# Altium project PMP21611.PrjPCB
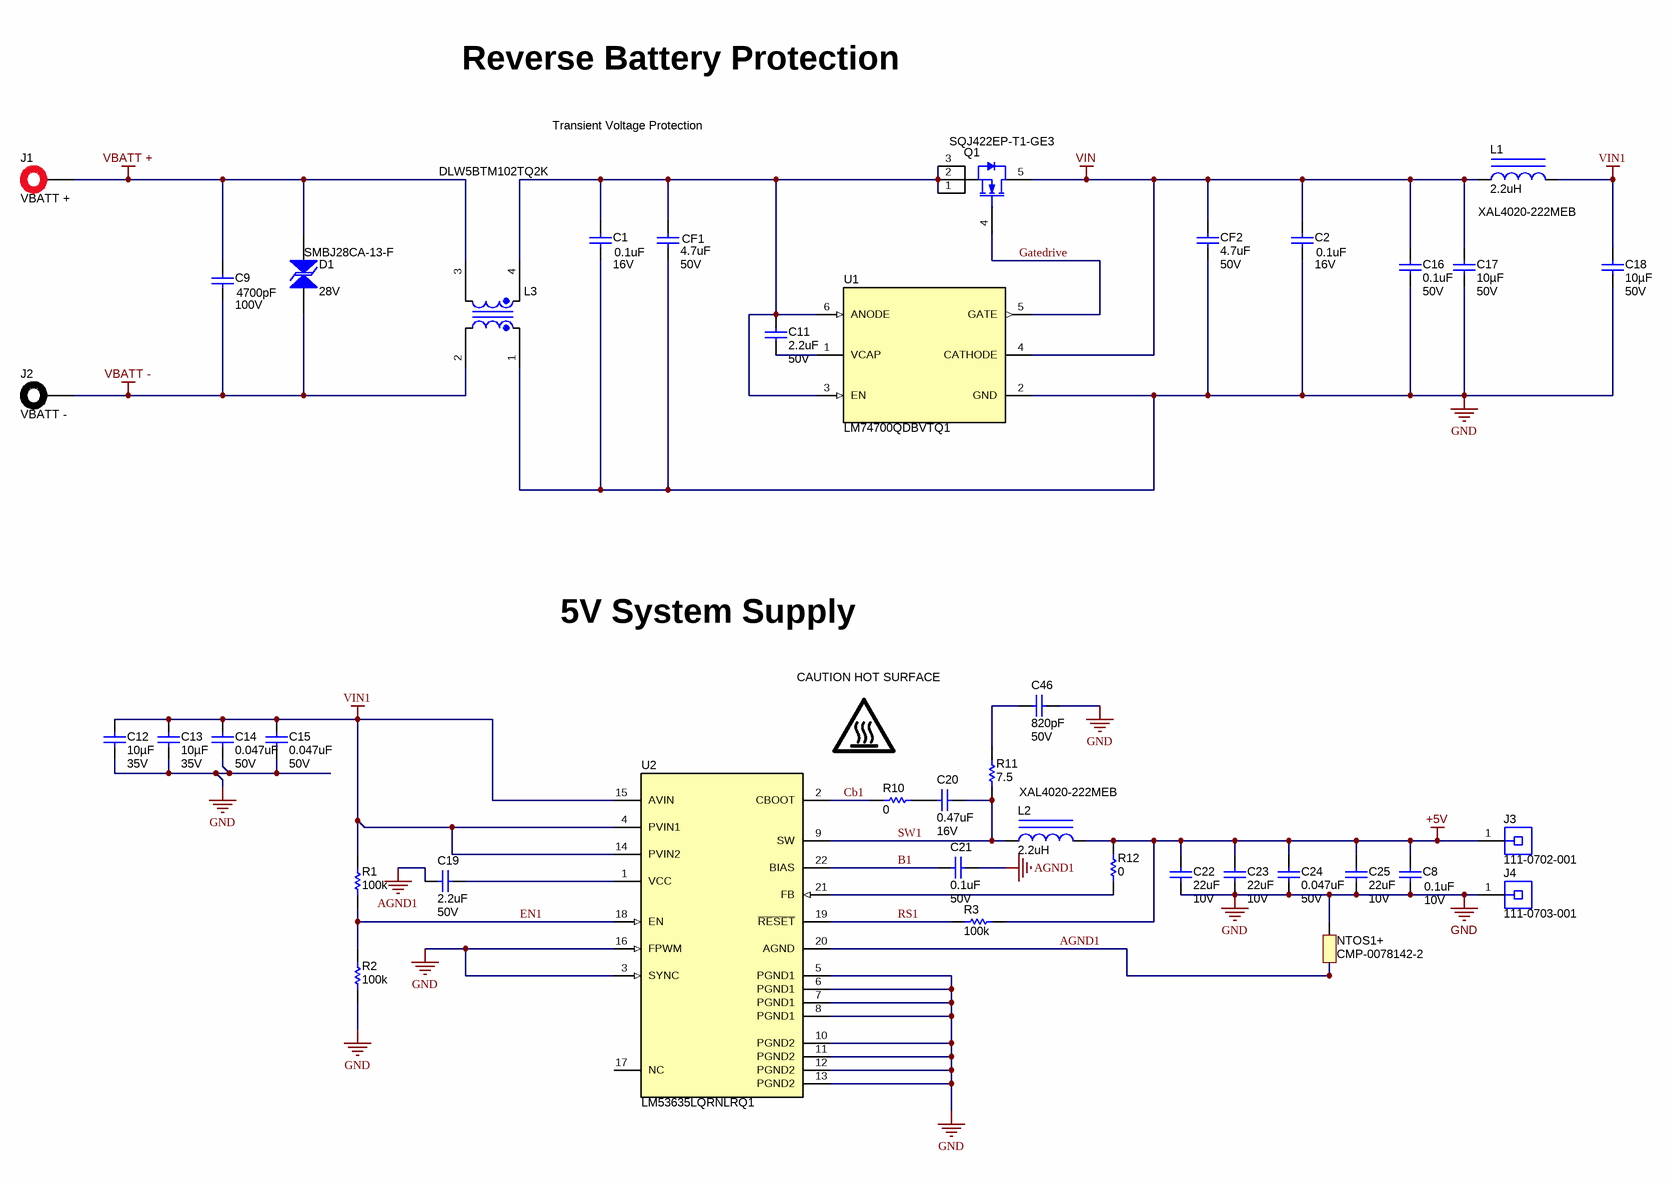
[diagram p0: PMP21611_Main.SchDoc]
CopyrightYear: 2018; EVM_Orderable: N/A; PCB_Layout: Dee Lim; PCB_Rev: A; PRJ_Customer: Public Release; PRJ_Engineer: R. Sheehan/ D. Foncannon; PRJ_Number: PMP21611; PRJ_Title: Automotive TFT Cluster Power Supply; SCH_Rev: A; TechSupport: http://www.ti.com/support
4 sheets, 96 parts. Net scope: global (net labels, ports and power ports of the same name join across sheets).
Board file: PMP21611.PcbDoc
Sheets:
  PMP21611_Cover.SchDoc
  PMP21611_Main.SchDoc
  PMP21611_Dual.SchDoc
  PMP21611_Hardware.SchDoc

## Sheet PMP21611_Cover.SchDoc
size 431 x 279 mm; Date: Not shown in title block; ApprovedBy: Not shown in title block; CheckedBy: Not shown in title block; Author: Not shown in title block; CompanyName: Not shown in title block; Engineer: Not shown in title block; Organization: Not shown in title block; Address1: Not shown in title block; Address2: Not shown in title block; Address3: Not shown in title block; Address4: Not shown in title block; DocumentNumber: 1; Revision: Use project parameter SCH_Rev; SheetNumber: 1; SheetTotal: 4; PageSetup: Record=PageOptions¦CenterHorizontal=True¦CenterVertical=True¦PrintScale=1.00¦XCorrection=1.00¦YCorrection=1.00¦PrintKind=0¦BorderSize=5000000¦LeftOffset=0¦BottomOffset=0¦Orientation=2¦PaperLength=1000¦PaperWidth=1000¦Scale=100¦PaperSource=15¦PrintQuality=600¦MediaType=1¦DitherType=10¦PaperKind=Letter¦PrintScaleMode=1

## Sheet PMP21611_Main.SchDoc
size 431 x 279 mm; Date: Not shown in title block; ApprovedBy: Not shown in title block; CheckedBy: Not shown in title block; Author: Not shown in title block; CompanyName: Not shown in title block; Engineer: Not shown in title block; Organization: Not shown in title block; Address1: Not shown in title block; Address2: Not shown in title block; Address3: Not shown in title block; Address4: Not shown in title block; DocumentNumber: 2; Revision: Use project parameter SCH_Rev; SheetNumber: 2; SheetTotal: 4; PageSetup: Record=PageOptions¦CenterHorizontal=True¦CenterVertical=True¦PrintScale=1.00¦XCorrection=1.00¦YCorrection=1.00¦PrintKind=0¦BorderSize=5000000¦LeftOffset=0¦BottomOffset=0¦Orientation=2¦PaperLength=1000¦PaperWidth=1000¦Scale=100¦PaperSource=15¦PrintQuality=600¦MediaType=1¦DitherType=10¦PaperKind=Letter¦PrintScaleMode=1

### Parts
(Parts that share a designator on the sheet are numbered #1, #2 ... from top to bottom, then left to right.)
C1  ValueDisplayed: 0.1uF  VDC_V: 16V  [0603]  (hidden comment: CMP-0007135-4)
C2  ValueDisplayed: 0.1uF  VDC_V: 16V  [0603]  (hidden comment: CMP-0007135-4)
C8  VDC_V: 10V  ValueDisplayed: 0.1uF  [0402]  (hidden comment: GCM155R71A104KA55D)
C9  ValueDisplayed: 4700pF  VDC_V: 100V  [0603]  (hidden comment: 06031C472KAT2A)
C11  ValueDisplayed: 2.2uF  VDC_V: 50V  [1206_180]  (hidden comment: C3216X7R1H225K160AB)
C12  ValueDisplayed: 10µF  VDC_V: 35V  [1210_270]  (hidden comment: GRM32ER7YA106KA12K)
C13  ValueDisplayed: 10µF  VDC_V: 35V  [1210_270]  (hidden comment: GRM32ER7YA106KA12K)
C14  ValueDisplayed: 0.047uF  VDC_V: 50V  [0603]  (hidden comment: C1608X7R1H473K080AA)
C15  ValueDisplayed: 0.047uF  VDC_V: 50V  [0603]  (hidden comment: C1608X7R1H473K080AA)
C16  ValueDisplayed: 0.1uF  VDC_V: 50V  [0805_HV]  (hidden comment: C0805C104K5RACTU)
C17  ValueDisplayed: 10µF  VDC_V: 50V  [1210_270]  (hidden comment: CL32B106KBJNNWE)
C18  ValueDisplayed: 10µF  VDC_V: 50V  [1210_270]  (hidden comment: CL32B106KBJNNWE)
C19  ValueDisplayed: 2.2uF  VDC_V: 50V  [1206_180]  (hidden comment: C3216X7R1H225K160AB)
C20  ValueDisplayed: 0.47uF  VDC_V: 16V  [0603]  (hidden comment: GCM188R71C474KA55D)
C21  ValueDisplayed: 0.1uF  VDC_V: 50V  [0603]  (hidden comment: GRM188R71H104KA93D)
C22  ValueDisplayed: 22uF  VDC_V: 10V  [1210_270]  (hidden comment: GRM32ER71A226ME20L)
C23  ValueDisplayed: 22uF  VDC_V: 10V  [1210_270]  (hidden comment: GRM32ER71A226ME20L)
C24  ValueDisplayed: 0.047uF  VDC_V: 50V  [0805_HV]  (hidden comment: 08055C473JAT2A)
C25  ValueDisplayed: 22uF  VDC_V: 10V  [1210_270]  (hidden comment: GRM32ER71A226ME20L)
C46  ValueDisplayed: 820pF  VDC_V: 50V  [0603]  (hidden comment: C0603C821K5RACTU)
CF1  ValueDisplayed: 4.7uF  VDC_V: 50V  [1210_280]  (hidden comment: CMP-0009163-2)
CF2  ValueDisplayed: 4.7uF  VDC_V: 50V  [1210_280]  (hidden comment: CMP-0009163-2)
D1  value 28V  PartNumber: SMBJ28CA-13-F  [SMB-Bi]  (hidden comment: CMP-0006046-2)
J1  VBATT +  [6091]
J2  VBATT -  [6092]
J3  111-0702-001  [Emerson_111-0702-001]
J4  111-0703-001  [Emerson_111-0703-001]
L1  PartNumber: XAL4020-222MEB  ValueDisplayed: 2.2uH  [XAL4020]  (hidden comment: CMP-0060986-1)
L2  PartNumber: XAL4020-222MEB  ValueDisplayed: 2.2uH  [XAL4020]  (hidden comment: CMP-0060986-1)
L3  PartNumber: DLW5BTM102TQ2K  [DLW5BT_TQ2]  (hidden comment: CMP-0076877-1)
LOGO4#1  CAUTION HOT SURFACE  [IEC_HotSurface_Small]  (no BOM)
NTOS1+  CMP-0078142-2  [Net-Tie_10mil]  (net tie, no BOM)
Q1  PartNumber: SQJ422EP-T1-GE3  [PowerPAK_SO-8L]  (hidden comment: CMP-0000747-1)
R1  ValueDisplayed: 100k  [0603]  (hidden comment: CRCW0603100KFKEA)
R2  ValueDisplayed: 100k  [0603]  (hidden comment: CRCW0603100KFKEA)
R3  ValueDisplayed: 100k  [0805_HV]  (hidden comment: CRCW0805100KFKEA)
R10  ValueDisplayed: 0  [0603]  (hidden comment: RMCF0603ZT0R00)
R11  ValueDisplayed: 7.5  [0603]  (hidden comment: CRCW06037R50JNEA)
R12  ValueDisplayed: 0  [0603]  (hidden comment: RMCF0603ZT0R00)
U1  LM74700QDBVTQ1  [DBV0006A_N]
U2  LM53635LQRNLRQ1  [RNL0022A]

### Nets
+5V: C8.1 C22.1 C23.1 C24.1 C25.1 J3.1 L2.2 R3.2 R12.2
AGND1: C19.2 C21.1 NTOS1+.1 U2.20(AGND)
GND: C1.2 C2.2 C8.2 C12.2 C13.2 C14.2 C15.2 C16.2 C17.2 C18.2 C22.2 C23.2 C24.2 C25.2 C46.2 CF1.2 CF2.2 J4.1 L3.1 NTOS1+.2 R2.1 U1.2(GND) U2.3(SYNC) U2.5(PGND1) U2.6(PGND1) U2.7(PGND1) U2.8(PGND1) U2.10(PGND2) U2.11(PGND2) U2.12(PGND2) U2.13(PGND2) U2.16(FPWM)
VBATT +: C9.1 D1.1 J1.1 L3.3
VBATT -: C9.2 D1.2 J2.1 L3.2
VIN: C2.1 C16.1 C17.1 CF2.1 L1.1 Q1.5(D) U1.4(CATHODE)
VIN1: C12.1 C13.1 C14.1 C15.1 C18.1 L1.2 R1.2 U2.4(PVIN1) U2.14(PVIN2) U2.15(AVIN)
B1: C21.2 U2.22(BIAS)
Cb1: R10.1 U2.2(CBOOT)
EN1: R1.1 R2.2 U2.18(EN)
Gatedrive: Q1.4(G) U1.5(GATE)
RS1: R3.1 U2.19(~{RESET})
SW1: C20.1 L2.1 R11.1 U2.9(SW)
NetC1_1: C1.1 C11.1 CF1.1 L3.4 Q1.1(S) Q1.2(S) Q1.3(S) U1.3(EN) U1.6(ANODE)
NetC11_2: C11.2 U1.1(VCAP)
NetC19_1: C19.1 U2.1(VCC)
NetC20_2: C20.2 R10.2
NetC46_1: C46.1 R11.2
NetR12_1: R12.1 U2.21(FB)

Not connected (* = marked no-connect by the designer): U2 17(NC)

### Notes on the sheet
- Reverse Battery Protection
- Transient Voltage Protection
- 5V System Supply

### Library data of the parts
C1 C2 = CMP-0007135-4: CAP, CERM, 0.1 uF, 16 V, +/- 10%, X7R, AEC-Q200 Grade 1, 0603; PartNumber: GCM188R71C104KA37J; Manufacturer: MuRata; Polarized: N; Value: 0.1uF; U/M: EA; Cap_F: 100nF; Value1: Unknown; TaMin_C: -55°C; TaMax_C: 125°C; AEC Category: Q200; AEC Qualified: Y; AEC Grade: 1; SizeArea_mm2: 1.28; SizeAreaWB_mm2: 4.68; SizeX_mm: 1.6; SizeY_mm: 0.8
C8 = CMP-0006350-2: CAP, CERM, 0.1 uF, 10 V, +/- 10%, X7R, AEC-Q200 Grade 1, 0402; Manufacturer: MuRata; TaMin_C: -55°C; Polarized: N; SizeAreaWB_mm2: 3; Value1: Unknown; U/M: EA; Value: 0.1uF; TaMax_C: 125°C; SizeZ_mm: 0.6; SizeX_mm: 1; SizeY_mm: 0.5; AEC Qualified: Y; Cap_F: 100nF; AEC Category: Q200
C9 = CMP-0006746-5: CAP, CERM, 4700 pF, 100 V, +/- 10%, X7R, 0603; Manufacturer: AVX; Polarized: N; Value: 4700pF; U/M: EA; Cap_F: 4.7nF; ESR_ohm: 1.36d; Value1: 0.136 ohm; TaMin_C: -55°C; TaMax_C: 125°C; SizeArea_mm2: 1.28; SizeAreaWB_mm2: 4.68; SizeX_mm: 1.6; SizeY_mm: 0.8; SizeZ_mm: 1; AEC Category: Q200
C11 = CMP-0008698-2: CAP, CERM, 2.2 uF, 50 V, +/- 10%, X7R, 1206; Manufacturer: TDK; Value: 2.2uF; Polarized: N; U/M: EA; Cap_F: 2.2µF; ESR_ohm: 5.887m; Value1: 0.005887 ohm; IRMS_A: 2.99226A; TaMin_C: -55°C; TaMax_C: 125°C; SizeAreaWB_mm2: 10.92; SizeZ_mm: 1.8; SizeX_mm: 3.2; SizeY_mm: 1.6; SizeArea_mm2: 5.12; AEC Category: Q200
C12 = CMP-0081639-1: CAP, CERM, 10 µF, 35 V,+/- 10%, X7R, 1210; Manufacturer: MuRata; Polarized: N; Value: 10uF; U/M: EA; ESR_ohm: 1m; Value1: 0.001 ohm; IRMS_A: 6A; TaMin_C: -55°C; TaMax_C: 125°C; Cap_Case: 1210; SizeAreaWB_mm2: 14.7; SizeZ_mm: 2.7; SizeX_mm: 3.2; SizeY_mm: 2.5; SizeArea_mm2: 8; AEC Category: Q200
C13 = CMP-0081639-1: CAP, CERM, 10 µF, 35 V,+/- 10%, X7R, 1210; Manufacturer: MuRata; Polarized: N; CompType: Capacitor; Value: 10uF; U/M: EA; ESR_ohm: 1m; Value1: 0.001 ohm; IRMS_A: 6A; TaMin_C: -55°C; TaMax_C: 125°C; Cap_Case: 1210; SizeAreaWB_mm2: 14.7; SizeZ_mm: 2.7; SizeX_mm: 3.2; SizeY_mm: 2.5; SizeArea_mm2: 8; AEC Category: Q200
C14 = CMP-0007049-4: CAP, CERM, 0.047 uF, 50 V, +/- 10%, X7R, 0603; Manufacturer: TDK; Polarized: N; U/M: EA; Cap_F: 47nF; ESR_ohm: 0.049007; Value1: 0.049007 ohm; IRMS_A: 7.67528dA; TaMin_C: -55°C; TaMax_C: 125°C; SizeAreaWB_mm2: 4.68; SizeZ_mm: 1; SizeX_mm: 1.6; SizeY_mm: 0.8; SizeArea_mm2: 1.28; AEC Category: Q200
C15 = CMP-0007049-4: CAP, CERM, 0.047 uF, 50 V, +/- 10%, X7R, 0603; Manufacturer: TDK; Polarized: N; CompType: Capacitor; U/M: EA; Cap_F: 47nF; ESR_ohm: 0.049007; Value1: 0.049007 ohm; IRMS_A: 7.67528dA; TaMin_C: -55°C; TaMax_C: 125°C; SizeAreaWB_mm2: 4.68; SizeZ_mm: 1; SizeX_mm: 1.6; SizeY_mm: 0.8; SizeArea_mm2: 1.28; AEC Category: Q200
C16 = CMP-0007726-2: CAP, CERM, 0.1 uF, 50 V, +/- 10%, X7R, 0805; Manufacturer: Kemet; Polarized: N; Value: 0.1uF; U/M: EA; Cap_F: 100nF; ESR_ohm: 0.064; Value1: 0.064 ohm; IRMS_A: 1.64A; TaMin_C: -55°C; TaMax_C: 125°C; Cap_Case: 0805; SizeAreaWB_mm2: 6.75; SizeZ_mm: 1.45; SizeX_mm: 2; SizeY_mm: 1.25; SizeArea_mm2: 2.5; AEC Category: Q200
C17 C18 = CMP-0079201-1: CAP, CERM, 10 µF, 50 V,+/- 10%, X7R, 1210; Manufacturer: Samsung Electro-Mechanics; Polarized: N; CompType: Capacitor; Value: 10uF; U/M: EA; ESR_ohm: 5m; Value1: 0.005 ohm; TaMin_C: -55°C; TaMax_C: 125°C; Cap_Case: 1210; SizeAreaWB_mm2: 14.7; SizeZ_mm: 2.7; SizeX_mm: 3.2; SizeY_mm: 2.5; SizeArea_mm2: 8; AEC Category: Q200
C19 = CMP-0008698-2: CAP, CERM, 2.2 uF, 50 V, +/- 10%, X7R, 1206; Manufacturer: TDK; Polarized: N; CompType: Capacitor; Value: 2.2uF; U/M: EA; Cap_F: 2.2µF; ESR_ohm: 5.887m; Value1: 0.005887 ohm; IRMS_A: 2.99226A; TaMin_C: -55°C; TaMax_C: 125°C; SizeAreaWB_mm2: 10.92; SizeZ_mm: 1.8; SizeX_mm: 3.2; SizeY_mm: 1.6; SizeArea_mm2: 5.12; AEC Category: Q200
C20 = CMP-0007138-4: CAP, CERM, 0.47 uF, 16 V, +/- 10%, X7R, AEC-Q200 Grade 1, 0603; Manufacturer: MuRata; Polarized: N; Value: 0.47uF; U/M: EA; Cap_F: 470nF; Value1: Unknown; TaMin_C: -55°C; TaMax_C: 125°C; SizeAreaWB_mm2: 4.68; SizeZ_mm: 1; SizeX_mm: 1.6; SizeY_mm: 0.8; SizeArea_mm2: 1.28; AEC Qualified: Y; AEC Category: Q200
C21 = CMP-0007434-4: CAP, CERM, 0.1 uF, 50 V, +/- 10%, X7R, 0603; Manufacturer: MuRata; Polarized: N; CompType: Capacitor; Value: 0.1uF; U/M: EA; Cap_F: 100nF; Value1: Unknown; TaMin_C: -55°C; TaMax_C: 125°C; SizeAreaWB_mm2: 4.68; SizeZ_mm: 1; SizeX_mm: 1.6; SizeY_mm: 0.8; SizeArea_mm2: 1.28; AEC Category: Q200
C22 C23 C25 = CMP-0009219-2: CAP, CERM, 22 uF, 10 V, +/- 10%, X7R, 1210; Manufacturer: MuRata; Polarized: N; CompType: Capacitor; Value: 22uF; U/M: EA; Cap_F: 22µF; ESR_ohm: 2m; Value1: 0.002 ohm; IRMS_A: 3.2A; TaMin_C: -55°C; TaMax_C: 125°C; Cap_Case: 1210; SizeAreaWB_mm2: 14.7; SizeZ_mm: 2.7; SizeX_mm: 3.2; SizeY_mm: 2.5; SizeArea_mm2: 8; AEC Category: Q200
C24 = CMP-0007658-2: CAP, CERM, 0.047 uF, 50 V, +/- 5%, X7R, 0805; Manufacturer: AVX; Polarized: N; CompType: Capacitor; U/M: EA; Cap_F: 47nF; ESR_ohm: 0.035; Value1: 0.035 ohm; TaMin_C: -55°C; TaMax_C: 125°C; Cap_Case: 0805; SizeAreaWB_mm2: 6.75; SizeZ_mm: 1.45; SizeX_mm: 2; SizeY_mm: 1.25; SizeArea_mm2: 2.5; AEC Category: Q200
C46 = CMP-0006972-5: CAP, CERM, 820 pF, 50 V, +/- 10%, X7R, 0603; Manufacturer: Kemet; Polarized: N; CompType: Capacitor; Value: 820pF; U/M: EA; Value1: Unknown; TaMin_C: -55°C; TaMax_C: 125°C; SizeAreaWB_mm2: 4.68; SizeZ_mm: 1; SizeX_mm: 1.6; SizeY_mm: 0.8; SizeArea_mm2: 1.28; AEC Category: Q200
CF1 CF2 = CMP-0009163-2: CAP, CERM, 4.7 uF, 50 V, +/- 20%, X7R, AEC-Q200 Grade 1, 1210; PartNumber: CGA6P3X7R1H475M250AB; Manufacturer: TDK; Polarized: N; Value: 4.7uF; U/M: EA; Cap_F: 4.7µF; Value1: Unknown; TaMin_C: -55°C; TaMax_C: 125°C; Cap_Case: 1210; AEC Category: Q200; AEC Qualified: Y; AEC Grade: 1; SizeAreaWB_mm2: 14.7; SizeZ_mm: 2.8; SizeX_mm: 3.2; SizeY_mm: 2.5; SizeArea_mm2: 8
D1 = CMP-0006046-2: Diode, TVS, Bi, 28 V, 45.4 Vc, SMB; Manufacturer: Diodes Inc.; U/M: EA; Power_W: 5W; AEC Category: Q101; AEC Qualified: N
J1 = CMP-0055167-2: Standard Banana Jack, Insulated, Red; Manufacturer: Keystone; CT: TRUE; Green_REACh: Passed; CNHeader: FALSE; Green_Lifecycle: Active
J2 = CMP-0055168-2: Standard Banana Jack, Insulated, Black; Manufacturer: Keystone; CT: TRUE; Green_REACh: Passed; CNHeader: FALSE; Green_Lifecycle: Active
J3 = CMP-0075036-1: Binding Post, Red, TH; Manufacturer: Cinch Connectivity; CT: False; CompType: Receptacle
J4 = CMP-0075035-1: Binding Post, Black, TH; Manufacturer: Cinch Connectivity; CT: False
L1 L2 = CMP-0060986-1: Inductor, Shielded, Composite, 2.2 uH, 5.5 A, 0.04 ohm, SMD; Manufacturer: Coilcraft; Value: 2.2uH; Ind_H: 2.2µH; Imax_A: 5.5A; Irms: 5.5A @ 40C rise; Isat: 5.62A @ 30% inductance drop; DCR_ohm: 0.04; Green_Lifecycle: Not Set; SizeAreaWB_mm2: 28.09; Green_REACh: Incomplete; SizeZ_mm: 2.1; SizeX_mm: 4.3; SizeArea_mm2: 18.49; AEC Category: Q200
L3 = CMP-0076877-1: Coupled inductor, 2.5 A, 0.034 ohm, SMD; Manufacturer: MuRata; DCR_ohm: 0.034; AEC Category: Q200
LOGO4#1 = IEC_HotSurface: IEC 61010-1 Hot Surface Warning; SymbolCreator: a0412235
NTOS1+ = CMP-0078142-2: Single point connection between nets.; CompType: Net-Tie
Q1 = CMP-0000747-1: MOSFET, N-CH, 40 V, 75 A, PowerPAK_SO-8L; Manufacturer: Vishay-Siliconix; Alternate Manufacturer: None; U/M: EA; ChType: N; Value: 40V; Value1: 0.004; Rdson45_ohm: 4.3m; Value2: 67 nC; QgTyp_nC: 67; Vgs_V: 20V; IdsMax_A: 75A; SizeZ_mm: 1.14; SizeX_mm: 6.15; SizeY_mm: 5.13; SizeArea_mm2: 31.5495; AEC Category: Q101; SizeAreaWB_mm2: 58.1095
R1 R2 = CMP-0021990-4: RES, 100 k, 1%, 0.1 W, AEC-Q200 Grade 0, 0603; Manufacturer: Vishay-Dale; CompType: Resistor; Value: 100k; Power_W: 100mW; Value2: 0.1W; VDC_V: 75V; TempCo: 100 ppm/C; EIA_Code: E96; SizeX_mm: 1.6; SizeY_mm: 0.8; SizeZ_mm: 1; SizeArea_mm2: 1.28; AEC Qualified: Y; AEC Category: Q200; AEC Grade: 0
R3 = CMP-0020834-3: RES, 100 k, 1%, 0.125 W, AEC-Q200 Grade 0, 0805; Manufacturer: Vishay-Dale; Value: 100k; Power_W: 125mW; Value2: 0.125W; VDC_V: 150V; TempCo: 100 ppm/C; EIA_Code: E96; SizeX_mm: 2; SizeY_mm: 1.25; SizeZ_mm: 1.45; SizeArea_mm2: 2.5; AEC Qualified: Y; AEC Category: Q200; AEC Grade: 0
R10 R12 = CMP-0023343-3: RES, 0, 1%, 0.1 W, AEC-Q200 Grade 0, 0603; Manufacturer: Stackpole Electronics Inc; Power_W: 100mW; TempCo: ppm/C; Value: 0; SizeX_mm: 1.6; SizeY_mm: 0.8; SizeZ_mm: 1; Value2: 0.1W; SizeArea_mm2: 1.28; CompType: Resistor; AEC Qualified: Y; AEC Category: Q200; U/M: EA
R11 = CMP-0025857-4: RES, 7.5, 5%, 0.1 W, AEC-Q200 Grade 0, 0603; Manufacturer: Vishay-Dale; CompType: Resistor; Value: 7.5; Value_Code: 7R50; Power_W: 100mW; Value2: 0.1W; VDC_V: 75V; TempCo: 200 ppm/C; EIA_Code: E24; SizeX_mm: 1.6; SizeY_mm: 0.8; SizeZ_mm: 1; SizeArea_mm2: 1.28; AEC Qualified: Y; AEC Category: Q200; AEC Grade: 0
U1 = CMP-0079180-1: Low Iq Always ON Smart Diode Controller, DBV0006A (SOT-23-6); Alternate PartNumber: LM74700QDBVRQ1; Manufacturer: Texas Instruments; SizeArea_mm2: 8.12; SizeAreaWB_mm2: 14.82; SizeX_mm: 2.8; SizeY_mm: 2.9; SizeZ_mm: 1.45; CompType: IC; AEC Qualified: Y; AEC Category: Q200
U2 = CMP-0076355-4: 3.5A, 36 V Synchronous, 2.1MHz, Automotive Step Down DC-DC Converter, RNL0022A (VQFN-HR-22); Manufacturer: Texas Instruments; Alternate PartNumber: LM53635LQRNLTQ1; SizeX_mm: 4.0; SizeY_mm: 5.0; CompType: IC; SizeZ_mm: 0.9; SizeArea_mm2: 20.0; SizeAreaWB_mm2: 42.0; AEC Category: Q200; AEC Qualified: Y

## Sheet PMP21611_Dual.SchDoc
size 431 x 279 mm; Date: Not shown in title block; ApprovedBy: Not shown in title block; CheckedBy: Not shown in title block; Author: Not shown in title block; CompanyName: Not shown in title block; Engineer: Not shown in title block; Organization: Not shown in title block; Address1: Not shown in title block; Address2: Not shown in title block; Address3: Not shown in title block; Address4: Not shown in title block; DocumentNumber: 3; Revision: Use project parameter SCH_Rev; SheetNumber: 3; SheetTotal: 4; PageSetup: Record=PageOptions¦CenterHorizontal=True¦CenterVertical=True¦PrintScale=1.00¦XCorrection=1.00¦YCorrection=1.00¦PrintKind=0¦BorderSize=5000000¦LeftOffset=0¦BottomOffset=0¦Orientation=2¦PaperLength=1000¦PaperWidth=1000¦Scale=100¦PaperSource=15¦PrintQuality=-3¦MediaType=1¦DitherType=10¦PrintScaleMode=1¦PaperKind=Letter¦PaperIndex=1
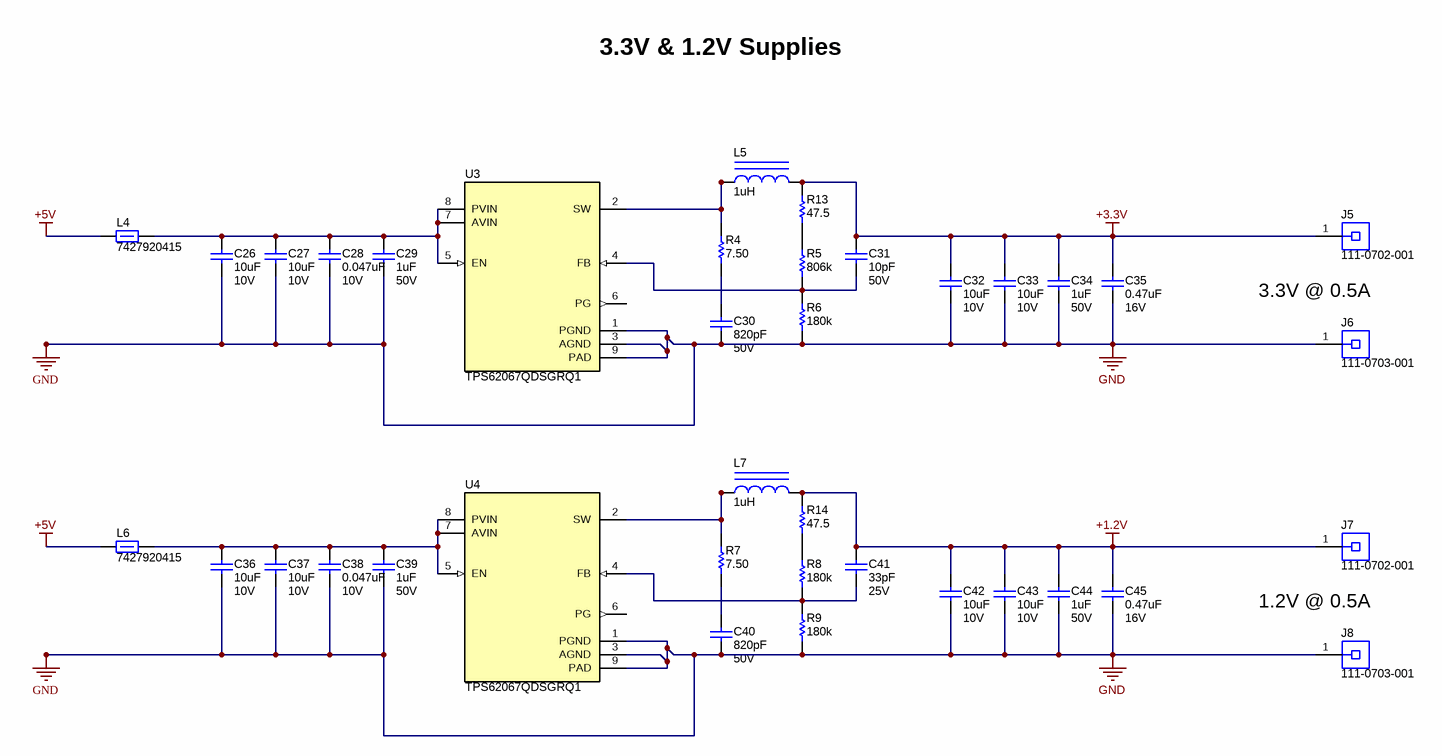
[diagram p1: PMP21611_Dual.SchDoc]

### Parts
C26  ValueDisplayed: 10uF  VDC_V: 10V  [0603]  (hidden comment: GRM188Z71A106MA73D)
C27  ValueDisplayed: 10uF  VDC_V: 10V  [0603]  (hidden comment: GRM188Z71A106MA73D)
C28  ValueDisplayed: 0.047uF  VDC_V: 10V  [0402]  (hidden comment: GRM155R71A473KA01D)
C29  ValueDisplayed: 1uF  VDC_V: 50V  [0603]  (hidden comment: UMK107AB7105KA-T)
C30  ValueDisplayed: 820pF  VDC_V: 50V  [0402]  (hidden comment: GRM155R71H821KA01D)
C31  ValueDisplayed: 10pF  VDC_V: 50V  [0402]  (hidden comment: 885012005055)
C32  ValueDisplayed: 10uF  VDC_V: 10V  [0603]  (hidden comment: GRM188Z71A106MA73D)
C33  ValueDisplayed: 10uF  VDC_V: 10V  [0603]  (hidden comment: GRM188Z71A106MA73D)
C34  ValueDisplayed: 1uF  VDC_V: 50V  [0603]  (hidden comment: UMK107AB7105KA-T)
C35  ValueDisplayed: 0.47uF  VDC_V: 16V  [0603]  (hidden comment: GCM188R71C474KA55D)
C36  ValueDisplayed: 10uF  VDC_V: 10V  [0603]  (hidden comment: GRM188Z71A106MA73D)
C37  ValueDisplayed: 10uF  VDC_V: 10V  [0603]  (hidden comment: GRM188Z71A106MA73D)
C38  ValueDisplayed: 0.047uF  VDC_V: 10V  [0402]  (hidden comment: GRM155R71A473KA01D)
C39  ValueDisplayed: 1uF  VDC_V: 50V  [0603]  (hidden comment: UMK107AB7105KA-T)
C40  ValueDisplayed: 820pF  VDC_V: 50V  [0402]  (hidden comment: GRM155R71H821KA01D)
C41  ValueDisplayed: 33pF  VDC_V: 25V  [0402]  (hidden comment: 885012005043)
C42  ValueDisplayed: 10uF  VDC_V: 10V  [0603]  (hidden comment: GRM188Z71A106MA73D)
C43  ValueDisplayed: 10uF  VDC_V: 10V  [0603]  (hidden comment: GRM188Z71A106MA73D)
C44  ValueDisplayed: 1uF  VDC_V: 50V  [0603]  (hidden comment: UMK107AB7105KA-T)
C45  ValueDisplayed: 0.47uF  VDC_V: 16V  [0603]  (hidden comment: GCM188R71C474KA55D)
J5  111-0702-001  [Emerson_111-0702-001]
J6  111-0703-001  [Emerson_111-0703-001]
J7  111-0702-001  [Emerson_111-0702-001]
J8  111-0703-001  [Emerson_111-0703-001]
L4  7427920415  [0805_HV]
L5  ValueDisplayed: 1uH  [DFE252012C]  (hidden comment: CMP-0058895-1)
L6  7427920415  [0805_HV]
L7  ValueDisplayed: 1uH  [DFE252012C]  (hidden comment: CMP-0058895-1)
R4  ValueDisplayed: 7.50  [0402]  (hidden comment: CMP-0026565-2)
R5  ValueDisplayed: 806k  [0402]  (hidden comment: CRCW0402806KFKED)
R6  ValueDisplayed: 180k  [0402]  (hidden comment: RC0402FR-07180KL)
R7  ValueDisplayed: 7.50  [0402]  (hidden comment: CMP-0026565-2)
R8  ValueDisplayed: 180k  [0402]  (hidden comment: RC0402FR-07180KL)
R9  ValueDisplayed: 180k  [0402]  (hidden comment: RC0402FR-07180KL)
R13  ValueDisplayed: 47.5  [0402]  (hidden comment: CRCW040247R5FKED)
R14  ValueDisplayed: 47.5  [0402]  (hidden comment: CRCW040247R5FKED)
U3  TPS62067QDSGRQ1  [DSG0008A]
U4  TPS62067QDSGRQ1  [DSG0008A]

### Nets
+1.2V: C41.1 C42.1 C43.1 C44.1 C45.1 J7.1 L7.2 R14.2
+3.3V: C31.1 C32.1 C33.1 C34.1 C35.1 J5.1 L5.2 R13.2
+5V: L4.1 L6.1
GND: C26.2 C27.2 C28.2 C29.2 C30.2 C32.2 C33.2 C34.2 C35.2 C36.2 C37.2 C38.2 C39.2 C40.2 C42.2 C43.2 C44.2 C45.2 J6.1 J8.1 R6.1 R9.1 U3.1(PGND) U3.3(AGND) U3.9(PAD) U4.1(PGND) U4.3(AGND) U4.9(PAD)
NetC26_1: C26.1 C27.1 C28.1 C29.1 L4.2 U3.5(EN) U3.7(AVIN) U3.8(PVIN)
NetC30_1: C30.1 R4.1
NetC31_2: C31.2 R5.1 R6.2 U3.4(FB)
NetC36_1: C36.1 C37.1 C38.1 C39.1 L6.2 U4.5(EN) U4.7(AVIN) U4.8(PVIN)
NetC40_1: C40.1 R7.1
NetC41_2: C41.2 R8.1 R9.2 U4.4(FB)
NetL5_1: L5.1 R4.2 U3.2(SW)
NetL7_1: L7.1 R7.2 U4.2(SW)
NetR5_2: R5.2 R13.1
NetR8_2: R8.2 R14.1

Not connected (* = marked no-connect by the designer): U3 6(PG); U4 6(PG)

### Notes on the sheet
- 3.3V & 1.2V Supplies
- 3.3V @ 0.5A
- 1.2V @ 0.5A

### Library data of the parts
C26 C32 C33 C36 C37 C42 C43 = CMP-0007497-5: CAP, CERM, 10 uF, 10 V, +/- 20%, X7R, 0603; Manufacturer: MuRata; Polarized: N; Value: 10uF; U/M: EA; Cap_F: 10µF; Value1: Unknown; TaMin_C: -55°C; TaMax_C: 125°C; SizeAreaWB_mm2: 4.68; SizeZ_mm: 1; SizeX_mm: 1.6; SizeY_mm: 0.8; SizeArea_mm2: 1.28; AEC Category: Q200
C27 = CMP-0007497-5: CAP, CERM, 10 uF, 10 V, +/- 20%, X7R, 0603; Manufacturer: MuRata; Polarized: N; CompType: Capacitor; Value: 10uF; U/M: EA; Cap_F: 10µF; Value1: Unknown; TaMin_C: -55°C; TaMax_C: 125°C; SizeAreaWB_mm2: 4.68; SizeZ_mm: 1; SizeX_mm: 1.6; SizeY_mm: 0.8; SizeArea_mm2: 1.28; AEC Category: Q200
C28 = CMP-0006634-2: CAP, CERM, 0.047 uF, 10 V, +/- 10%, X7R, 0402; Manufacturer: MuRata; Polarized: N; CompType: Capacitor; U/M: EA; Cap_F: 47nF; Value1: Unknown; TaMin_C: -55°C; TaMax_C: 125°C; SizeAreaWB_mm2: 3; SizeZ_mm: 0.6; SizeX_mm: 1; SizeY_mm: 0.5; AEC Category: Q200
C29 C39 = CMP-0007508-5: CAP, CERM, 1 uF, 50 V, +/- 10%, X7R, 0603; Manufacturer: Taiyo Yuden; Polarized: N; Value: 1uF; U/M: EA; Cap_F: 1µF; Value1: Unknown; TaMin_C: -55°C; TaMax_C: 125°C; SizeAreaWB_mm2: 4.68; SizeZ_mm: 1; SizeX_mm: 1.6; SizeY_mm: 0.8; SizeArea_mm2: 1.28; AEC Category: Q200
C30 = CMP-0006697-2: CAP, CERM, 820 pF, 50 V, +/- 10%, X7R, 0402; Manufacturer: MuRata; Polarized: N; CompType: Capacitor; Value: 820pF; U/M: EA; Value1: Unknown; TaMin_C: -55°C; TaMax_C: 125°C; SizeAreaWB_mm2: 3; SizeZ_mm: 0.6; SizeX_mm: 1; SizeY_mm: 0.5; AEC Category: Q200
C31 = CMP-0006215-2: CAP, CERM, 10 pF, 50 V, +/- 5%, C0G/NP0, 0402; Manufacturer: Wurth Elektronik; Polarized: N; CompType: Capacitor; Value: 10pF; U/M: EA; Value1: Unknown; TaMin_C: -55°C; TaMax_C: 125°C; SizeAreaWB_mm2: 3; SizeZ_mm: 0.6; SizeX_mm: 1; SizeY_mm: 0.5; AEC Category: Q200
C34 C44 = CMP-0007508-5: CAP, CERM, 1 uF, 50 V, +/- 10%, X7R, 0603; Manufacturer: Taiyo Yuden; Polarized: N; CompType: Capacitor; Value: 1uF; U/M: EA; Cap_F: 1µF; Value1: Unknown; TaMin_C: -55°C; TaMax_C: 125°C; SizeAreaWB_mm2: 4.68; SizeZ_mm: 1; SizeX_mm: 1.6; SizeY_mm: 0.8; SizeArea_mm2: 1.28; AEC Category: Q200
C35 C45 = CMP-0007138-4: as C20 on sheet PMP21611_Main
C38 = CMP-0006634-2: CAP, CERM, 0.047 uF, 10 V, +/- 10%, X7R, 0402; Manufacturer: MuRata; Polarized: N; U/M: EA; Cap_F: 47nF; Value1: Unknown; TaMin_C: -55°C; TaMax_C: 125°C; SizeAreaWB_mm2: 3; SizeZ_mm: 0.6; SizeX_mm: 1; SizeY_mm: 0.5; AEC Category: Q200
C40 = CMP-0006697-2: CAP, CERM, 820 pF, 50 V, +/- 10%, X7R, 0402; Manufacturer: MuRata; Polarized: N; Value: 820pF; U/M: EA; Value1: Unknown; TaMin_C: -55°C; TaMax_C: 125°C; SizeAreaWB_mm2: 3; SizeZ_mm: 0.6; SizeX_mm: 1; SizeY_mm: 0.5; AEC Category: Q200
C41 = CMP-0006213-2: CAP, CERM, 33 pF, 25 V, +/- 5%, C0G/NP0, 0402; Manufacturer: Wurth Elektronik; Polarized: N; CompType: Capacitor; Value: 33pF; U/M: EA; Value1: Unknown; TaMin_C: -55°C; TaMax_C: 125°C; SizeAreaWB_mm2: 3; SizeZ_mm: 0.6; SizeX_mm: 1; SizeY_mm: 0.5; AEC Category: Q200
J5 J7 = CMP-0075036-1: as J3 on sheet PMP21611_Main
J6 J8 = CMP-0075035-1: as J4 on sheet PMP21611_Main
L4 L6 = CMP-0003086-1: Ferrite Bead, 600 ohm @ 100 MHz, 0.5 A, 0805; Manufacturer: Wurth Elektronik; Value: 600 ohm; Imax_A: 5dA; DCR_ohm: 3d; Value1: 0.3 ohm; Value2: 0.5A; SizeAreaWB_mm2: 6.75; SizeZ_mm: 1.45; SizeX_mm: 2; SizeY_mm: 1.25; SizeArea_mm2: 2.5; Ztyp@1GHz_Ohm: 141.542; ZTyp@100MHz_Ohm: 600
L5 L7 = CMP-0058895-1: Inductor, Shielded, Ferrite, 1 uH, 3 A, 0.045 ohm, SMD; PartNumber: 1239AS-H-1R0M=P2; Manufacturer: MuRata Toko; Value: 1uH; Ind_H: 1µH; Imax_A: 3A; Irms: 3A @ 40C rise; Isat: 3A @ 30% inductance drop; DCR_ohm: 0.045; AEC Category: Q200; SizeAreaWB_mm2: 11.84; SizeZ_mm: 1.2; SizeX_mm: 2.7; SizeY_mm: 2.2; SizeArea_mm2: 5.94
R4 = CMP-0026565-2: RES, 7.50, 1%, 0.063 W, AEC-Q200 Grade 0, 0402; PartNumber: CRCW04027R50FKED; Manufacturer: Vishay-Dale; CompType: Resistor; Value: 7.50; Res_ohm: 7.5; Value_Code: 7R50; Power_W: 63mW; Value2: 0.063W; VDC_V: 50V; TempCo: 100 ppm/C; EIA_Code: E96; SizeX_mm: 1; SizeY_mm: 0.5; SizeZ_mm: 0.6; AEC Qualified: Y; AEC Category: Q200; AEC Grade: 0
R5 = CMP-0026568-2: RES, 806 k, 1%, 0.063 W, AEC-Q200 Grade 0, 0402; Manufacturer: Vishay-Dale; Value: 806k; Power_W: 63mW; Value2: 0.063W; VDC_V: 50V; TempCo: 100 ppm/C; EIA_Code: E96; SizeX_mm: 1; SizeY_mm: 0.5; SizeZ_mm: 0.6; AEC Qualified: Y; AEC Category: Q200; AEC Grade: 0
R6 R8 = CMP-0026723-1: RES, 180 k, 1%, 0.063 W, 0402; Manufacturer: Yageo America; Value: 180k; Power_W: 63mW; Value2: 0.063W; VDC_V: 50V; TempCo: 100 ppm/C; SizeX_mm: 1; SizeY_mm: 0.5; SizeZ_mm: 0.6; AEC Qualified: N; AEC Category: Q200; U/M: EA
R7 = CMP-0026565-2: RES, 7.50, 1%, 0.063 W, AEC-Q200 Grade 0, 0402; PartNumber: CRCW04027R50FKED; Manufacturer: Vishay-Dale; Value: 7.50; Res_ohm: 7.5; Value_Code: 7R50; Power_W: 63mW; Value2: 0.063W; VDC_V: 50V; TempCo: 100 ppm/C; EIA_Code: E96; SizeX_mm: 1; SizeY_mm: 0.5; SizeZ_mm: 0.6; AEC Qualified: Y; AEC Category: Q200; AEC Grade: 0
R9 = CMP-0026723-1: RES, 180 k, 1%, 0.063 W, 0402; Manufacturer: Yageo America; CompType: Resistor; Value: 180k; Power_W: 63mW; Value2: 0.063W; VDC_V: 50V; TempCo: 100 ppm/C; SizeX_mm: 1; SizeY_mm: 0.5; SizeZ_mm: 0.6; AEC Qualified: N; AEC Category: Q200; U/M: EA
R13 R14 = CMP-0026396-2: RES, 47.5, 1%, 0.063 W, AEC-Q200 Grade 0, 0402; Manufacturer: Vishay-Dale; Power_W: 63mW; TempCo: 100 ppm/C; Value_Code: 47R5; Value: 47.5; EIA_Code: E96; SizeX_mm: 1; SizeY_mm: 0.5; SizeZ_mm: 0.6; Value2: 0.063W; AEC Qualified: Y; VDC_V: 50V; AEC Category: Q200; AEC Grade: 0
U3 U4 = CMP-0081411-1: 3MHz, 2A Automotive Step-Down Converter in 2x2 SON Package, DSG0008A (WSON-8); Manufacturer: Texas Instruments; SizeAreaWB_mm2: 9; SizeZ_mm: 0.8; SizeX_mm: 2; SizeArea_mm2: 4; CompType: IC; AEC Qualified: Y; AEC Category: Q200

## Sheet PMP21611_Hardware.SchDoc
size 431 x 279 mm; Date: Not shown in title block; ApprovedBy: Not shown in title block; CheckedBy: Not shown in title block; Author: Not shown in title block; CompanyName: Not shown in title block; Engineer: Not shown in title block; Organization: Not shown in title block; Address1: Not shown in title block; Address2: Not shown in title block; Address3: Not shown in title block; Address4: Not shown in title block; DocumentNumber: 4; Revision: Use project parameter SCH_Rev; SheetNumber: 4; SheetTotal: 4; PageSetup: Record=PageOptions¦CenterHorizontal=True¦CenterVertical=True¦PrintScale=1.00¦XCorrection=1.00¦YCorrection=1.00¦PrintKind=0¦BorderSize=5000000¦LeftOffset=0¦BottomOffset=0¦Orientation=2¦PaperLength=1000¦PaperWidth=1000¦Scale=100¦PaperSource=15¦PrintQuality=600¦MediaType=1¦DitherType=10¦PaperKind=Letter¦PrintScaleMode=1
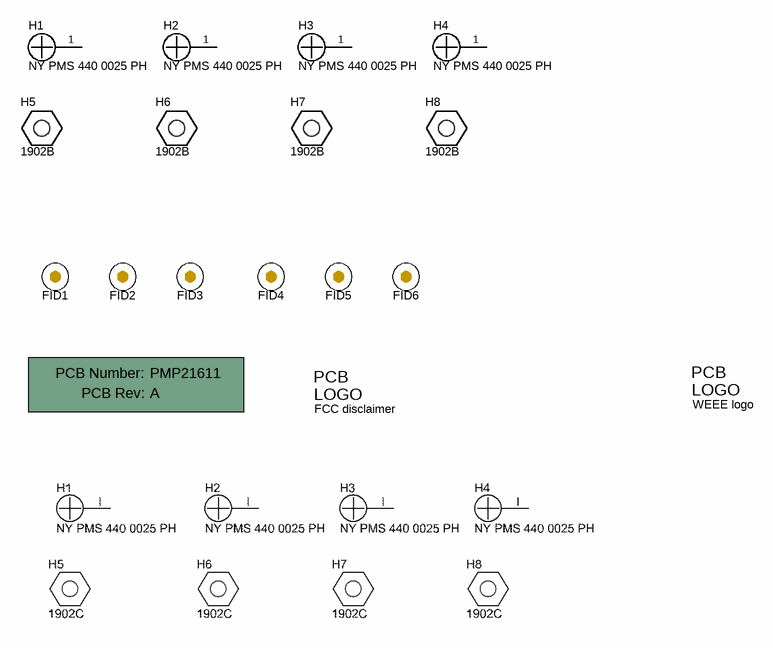
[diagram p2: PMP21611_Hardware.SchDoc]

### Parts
(Parts that share a designator on the sheet are numbered #1, #2 ... from top to bottom, then left to right.)
!PCB1  Printed Circuit Board  (value not drawn)  (mechanical)
FID1  Fiducial  [Fiducial10-20]  (value not drawn)
FID2  Fiducial  [Fiducial10-20]  (value not drawn)
FID3  Fiducial  [Fiducial10-20]  (value not drawn)
FID4  Fiducial  [Fiducial10-20]  (value not drawn)
FID5  Fiducial  [Fiducial10-20]  (value not drawn)
FID6  Fiducial  [Fiducial10-20]  (value not drawn)
H1  NY PMS 440 0025 PH  [NY PMS 440 0025 PH]
H2  NY PMS 440 0025 PH  [NY PMS 440 0025 PH]
H3  NY PMS 440 0025 PH  [NY PMS 440 0025 PH]
H4  NY PMS 440 0025 PH  [NY PMS 440 0025 PH]
H5  1902B  [Keystone_1902B]
H6  1902B  [Keystone_1902B]
H7  1902B  [Keystone_1902B]
H8  1902B  [Keystone_1902B]
Logo3  FCC disclaimer  [FCC_disclaimer]  (no BOM)
Logo4#2  WEEE logo  [WEEE_Minimum]  (no BOM)

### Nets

Not connected (* = marked no-connect by the designer): H1 1; H2 1; H3 1; H4 1

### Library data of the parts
!PCB1 = PCB: Manufacturer: Any; PartNumber: PMP21611; SymbolCreator: a0412235
FID1-FID6 = Fiducial: Fiducial mark.  There is nothing to buy or mount.; SymbolCreator: codlsc
H1-H4 = CMP-0003617-1: Machine Screw, Round, #4-40 x 1/4, Nylon, Philips panhead; Manufacturer: B&F Fastener Supply; CompType: Hardware
H5-H8 = CMP-0003658-1: Manufacturer: Keystone; CompType: Hardware
Logo3 = FCC_disclaimer: SymbolCreator: codlsc
Logo4#2 = CMP-0074769-1

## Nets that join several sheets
+5V: PMP21611_Main (9 pins), PMP21611_Dual (L4.1 L6.1)
GND: PMP21611_Main (32 pins), PMP21611_Dual (28 pins)

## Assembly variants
001: not fitted C46 R11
